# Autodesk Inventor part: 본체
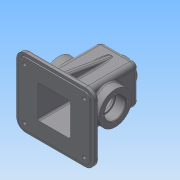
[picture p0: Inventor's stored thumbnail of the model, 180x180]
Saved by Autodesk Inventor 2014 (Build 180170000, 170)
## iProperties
Created: 2015-12
Part Number: 본체
Material: Generic
Document SubType Name: Modeling
Designer: Administrator
Density: 1 g/cm^3
Appearance: Default
Author: Administrator
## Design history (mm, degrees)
sketch "스케치1"
  geometry: L1 (32.5, -55)-(-32.5, -55); L2 (-32.5, -55)-(-32.5, 55); L3 (-32.5, 55)-(32.5, 55); L4 (32.5, 55)-(32.5, -55); L5 (32.5, -55)-(-32.5, 55); L6 (-32.5, -55)-(32.5, 55); 1 further point
  constraints: 12 end point, 2 midpoint, 2 parallel, 1 horizontal, 1 perpendicular
  dimensions: "d0" = 65 distance of L2.end L3.end; "d1" = 110 distance of L1.end L2.end
extrude "돌출1" new body sketch "스케치1" stored distance "d2" = 65; taper "d3" = 0 deg
sketch "스케치2"
  geometry: C1 r 20 at (32.5, 32.5); 1 further point
  constraints: 1 centre point, 1 coincident
  dimensions: "d4" = 40 diameter of C1
extrude "돌출2" join sketch "스케치2" distance "d5" = 10; taper "d6" = -5 deg
sketch "스케치3"
  geometry: C1 r 27.5 at (-32.5, 55); 1 further point
  constraints: 1 centre point, 1 coincident
  dimensions: "d7" = 55 diameter of C1
extrude "돌출3" join sketch "스케치3" distance "d8" = 15; taper "d9" = 0 deg
sketch "스케치4"
  geometry: C1 r 27.5 at (32.5, 55); 1 further point
  constraints: 1 centre point, 1 coincident
  dimensions: "d10" = 55 diameter of C1
extrude "돌출4" join sketch "스케치4" distance "d11" = 15; taper "d12" = 0 deg
sketch "스케치6"
  geometry: L1 (65, -65)-(65, 0) reference; L2 (0, 0)-(65, 0) reference; L3 (0, 0)-(0, -65) reference; L4 (65, -65)-(0, -65) reference; L5 (82.5, -85)-(-17.5, -85); L6 (-27.5, -75)-(-27.5, 10); L7 (-17.5, 20)-(82.5, 20); L8 (92.5, 10)-(92.5, -75); L9 (92.5, -85)-(-27.5, 20); L10 (-27.5, -85)-(92.5, 20); A1 r 10 centre (-17.5, 10) between (-17.5, 20) and (-27.5, 10); A2 r 10 centre (-17.5, -75) between (-27.5, -75) and (-17.5, -85); A3 r 10 centre (82.5, -75) between (82.5, -85) and (92.5, -75); A4 r 10 centre (82.5, 10) between (92.5, 10) and (82.5, 20); 1 further point
  constraints: 12 end point, 8 point on circle, 8 point on line, 8 tangent, 4 centre point, 3 equal radius, 2 midpoint, 2 parallel, 1 horizontal, 1 perpendicular
  dimensions: "d13" = 120 distance of L9.end L10.end; "d14" = 105 distance of L10.start L9.end; "d90" = 10 radius of A1
extrude "돌출5" join sketch "스케치6" distance "d15" = 2; taper "d16" = 0 deg
sketch "스케치7"
  geometry: L1 (-32.5, -25)-(97.5, -25); L2 (97.5, -25)-(97.5, 90); L3 (97.5, 90)-(-32.5, 90); L4 (-32.5, 90)-(-32.5, -25); L5 (-32.5, -25)-(97.5, 90); L6 (97.5, -25)-(-32.5, 90); 1 further point
  constraints: 12 end point, 2 midpoint, 2 parallel, 1 horizontal, 1 perpendicular
  dimensions: "d17" = 130 distance of L3.end L2.end; "d18" = 115 distance of L2.end L1.end
extrude "돌출6" join sketch "스케치7" distance "d19" = 8; taper "d20" = 0 deg
sketch "스케치8"
  geometry: L1 (-27.5, 75)-(-27.5, -10) reference; L2 (92.5, -10)-(92.5, 75) reference; L3 (82.5, 85)-(-17.5, 85) reference; L4 (-17.5, -20)-(82.5, -20) reference; L5 (-32.5, -25)-(97.5, -25) reference; L6 (97.5, 90)-(-32.5, 90) reference; L7 (-32.5, 90)-(-32.5, -25) reference; L8 (65, 0)-(65, 65) reference; L9 (32.5, 32.5)-(32.5, 46.814); C1 r 7.5 at (-17.5, 75); C2 r 7.5 at (-17.5, -10); C3 r 7.5 at (82.5, 75); C4 r 7.5 at (82.5, -10)
  constraints: 4 centre point, 2 end point, 2 symmetric about line, 1 parallel, 2 other
  dimensions: "d21" = 15 diameter of C1; "d91" = 15 distance from line of C1.centre L7; "d92" = 15 distance from line of C1.centre L6; "d93" = 15 diameter of C2; "d94" = 15 distance from line of C2.centre L7; "d95" = 15 distance from line of L5 C2.centre
extrude "돌출7" join sketch "스케치8" distance "d27" = 3; taper "d28" = 0 deg
sketch "스케치11"
  geometry: L1 (-55, 27.5)-(50, 27.5); L2 (50, 27.5)-(50, -27.5); L3 (50, -27.5)-(-55, -27.5); L4 (-55, -27.5)-(-55, 27.5); L5 (55, 32.5)-(55, -32.5) reference; L6 (-55, -42.5)-(-55, 42.5) reference; 2 further points
  constraints: 8 end point, 2 parallel, 1 horizontal, 1 perpendicular
  dimensions: "d32" = 55 distance of L1.end L2.end; "d33" = 5 distance between parallel lines of L2 L5; "d34" = 0 distance between parallel lines of L4 L6; "d35" = 5 distance from line of L5.start L1
extrude "돌출9" cut sketch "스케치11" stored distance "d36" = 55; taper "d37" = 0 deg
sketch "스케치12"
  geometry: C1 r 19.125 at (0, 0) reference; C2 r 10.5 at (0, 0)
  constraints: 1 centre point, 1 coincident
  dimensions: "d38" = 21 diameter of C2
extrude "돌출10" cut sketch "스케치12" distance "d39" = 30; taper "d40" = 0 deg
sketch "스케치14"
  geometry: L1 (0, 21)-(0, 0); L2 (0, 0)-(-21, 0); L3 (0, 0)-(0, -21); L4 (0, 0)-(21, 0); C1 r 27.5 at (0, 0) reference
  constraints: 8 end point, 3 perpendicular, 1 vertical
  dimensions: "d45" = 21 distance from line of L4.end L1; "d46" = 21 distance from line of L1.start L2; "d47" = 21 distance from line of L3.end L2; "d48" = 21 distance from line of L2.end L1
hole "구멍1" sketch "스케치14" at (0, 21), (-21, 0), (0, -21), (21, 0) diameter "d49" = 3.242; stored, may be unused: countersink angle "d53" = 90 deg, drill point angle "d55" = 118 deg; dims "d50" = 8, "d51" = 4, "d52" = 2, "d54" = 10
sketch "스케치15"
  geometry: L1 (0, 14.5)-(0, -14.5); L2 (-14.5, 0)-(14.5, 0); C1 r 10.5 at (0, 0) reference
  constraints: 4 end point, 1 perpendicular, 1 vertical
  dimensions: "d57" = 0 distance from line of C1.centre L2; "d58" = 0 distance from line of C1.centre L1; "d59" = 14.5 distance from line of L2.end L1; "d60" = 14.5 distance from line of L1.start L2; "d61" = 14.5 distance from line of L1.end L2; "d62" = 14.5 distance from line of L2.start L1
hole "구멍2" sketch "스케치15" at (0, 14.5), (-14.5, 0), (14.5, 0), (0, -14.5) diameter "d63" = 2.459; stored, may be unused: countersink angle "d67" = 90 deg, drill point angle "d69" = 118 deg; dims "d64" = 7, "d65" = 4, "d66" = 2, "d68" = 9
sketch "스케치16"
  geometry: L1 (-45, -57.5)-(-45, 57.5) reference; L2 (-45, 57.5)-(-45, 47.5); L3 (-45, 47.5)-(50.41, 30.677); L4 (50.41, 30.677)-(-45, 30.677); L5 (-45, 47.5)-(-45, 30.677); 1 further point
  constraints: 8 end point, 2 point on line, 1 collinear, 1 perpendicular
  dimensions: "d70" = 10 distance of L1.end L2.end; "d71" = 100 deg angle of L3 L2
extrude "돌출12" join sketch "스케치16" stored distance "d72" = 10; taper "d73" = 0 deg
sketch "스케치17"
  geometry: L1 (-32.5, -27.5)-(-47.5, -27.5) reference; L2 (-32.5, -45)-(-32.5, 55) reference; L3 (65, -45)-(-65, -45) reference; L4 (-42.5, -25.832)-(-42.5, -49.613); L5 (-27.5, 50)-(-27.5, -55) reference; L6 (-42.5, -25.832)-(-30.479, -25.832); L7 (-30.479, -25.832)-(-30.479, -49.613); L8 (-30.479, -49.613)-(-42.5, -49.613); 1 further point
  constraints: 8 end point, 3 perpendicular, 1 parallel
  dimensions: "d74" = 15 distance between parallel lines of L5 L4; "d75" = 2.02132 distance between parallel lines of L2 L7; "d76" = 1.66847 distance between parallel lines of L1 L6; "d77" = 22.11306 distance between parallel lines of L1 L8
extrude "돌출13" join sketch "스케치17" stored distance "d78" = 6; taper "d79" = 0 deg
sketch "스케치18"
  geometry: L1 (0, -100)-(0, 0) reference; L2 (13.375, 10)-(51.625, 10) reference; 1 further point
  constraints: 1 other
  dimensions: "d80" = 32.5 distance from line of point (32.5, -16) L1; "d81" = 26 distance from line of point (32.5, -16) L2
feature "엠보싱1" sketch "스케치18" dims "d82" = 0.5, "d83" = 0
fillet "모깎기1" dims "d84" = 8
fillet "모깎기2" dims "d85" = 8
chamfer "모따기1" distance "d86" = 1; stored, may be unused: second distance "d87" = 2, angle "d88" = 45 deg
fillet "모깎기3" dims "d89" = 15
sketch "스케치19"
  geometry: C1 r 7.5 at (0, 0) reference; C2 r 3 at (0, 0); C3 r 7.5 at (100, 0) reference; C4 r 7.5 at (100, -85) reference; C5 r 7.5 at (0, -85) reference; C6 r 3 at (0, -85); C7 r 3 at (100, -85); C8 r 3 at (100, 0); 1 further point
  constraints: 4 centre point, 4 coincident
  dimensions: "d96" = 6 diameter of C2; "d97" = 6 diameter of C6; "d98" = 6 diameter of C7; "d99" = 6 diameter of C8
extrude "돌출14" cut sketch "스케치19" stored distance "d100" = 6; taper "d101" = 0 deg
fillet "모깎기4" dims "d102" = 3
fillet "모깎기5" dims "d103" = 3
fillet "모깎기6" dims "d104" = 3
fillet "모깎기7" dims "d105" = 3
fillet "모깎기8" dims "d106" = 3
fillet "모깎기9" dims "d107" = 3
fillet "모깎기10" dims "d108" = 3
sketch "스케치20"
  geometry: C1 r 27.5 at (0, 0) reference; C2 r 17.5 at (0, 0)
  constraints: 1 centre point, 1 coincident
  dimensions: "d109" = 35 diameter of C2
extrude "돌출15" cut sketch "스케치20" distance "d110" = 17; taper "d111" = 0 deg
sketch "스케치22"
  geometry: C1 r 27.5 at (0, 0) reference; C2 r 17.5 at (0, 0)
  constraints: 1 centre point, 1 coincident
  dimensions: "d112" = 35 diameter of C2
extrude "돌출16" cut sketch "스케치22" distance "d113" = 17; taper "d114" = 0 deg
sketch "스케치23"
  geometry: C1 r 17.5 at (0, 0) reference; C2 r 15 at (0, 0)
  constraints: 1 centre point, 1 coincident
  dimensions: "d115" = 30 diameter of C2
extrude "돌출17" cut sketch "스케치23" stored distance "d116" = 17; taper "d117" = 0 deg
chamfer "모따기2" distance "d118" = 1; stored, may be unused: second distance "d119" = 2, angle "d120" = 45 deg
fillet "모깎기11" dims "d121" = 0.3
fillet "모깎기12" dims "d122" = 3
node "솔리드1"
mirror "대칭1"
mirror "대칭2"
mirror "대칭3"
node "투영된 루프1"
